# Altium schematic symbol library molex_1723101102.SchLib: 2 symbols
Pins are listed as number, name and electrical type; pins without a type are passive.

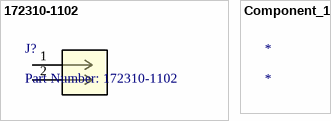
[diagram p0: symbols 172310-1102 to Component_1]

## 172310-1102
designator J?, comment Part Number: 172310-1102
No Description Available; Vendor: Molex Connector Corporation; Built_By: EMA_Cory
footprint CONN_172310-1102
pins: 1, 2

## Component_1
designator *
